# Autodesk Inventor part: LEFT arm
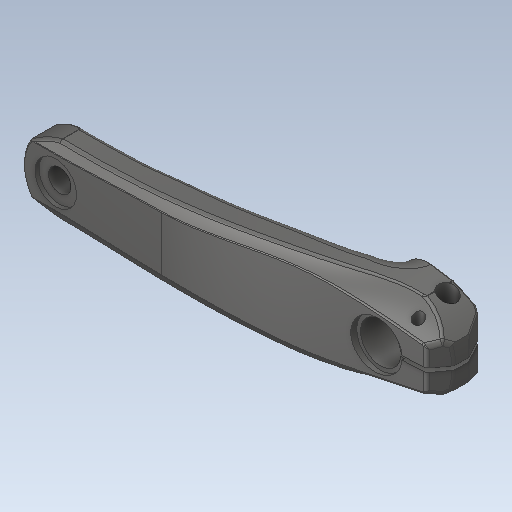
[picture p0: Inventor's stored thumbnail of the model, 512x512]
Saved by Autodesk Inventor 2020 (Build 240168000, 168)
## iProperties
Created: 2015-11
Part Number: LEFT arm
Material: solidworks materials|6061-T6 (SS)|164
Document SubType Name: Modeling
Designer: Tomasz
Density: 2.7 g/cm^3
Appearance: 221,232,255
Sending System: SolidWorks 2017
Last Author: Tomasz
Last Saved: 2017-10-01
Author: Tomasz
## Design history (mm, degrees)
feature "Imported1"
node "Bryła1"
